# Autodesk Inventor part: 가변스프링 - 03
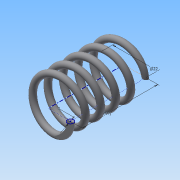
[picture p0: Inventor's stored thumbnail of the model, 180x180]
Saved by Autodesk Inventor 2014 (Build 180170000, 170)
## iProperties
Created: 2015-09
Part Number: 가변스프링 - 03
Material: 강철, 탄소
Document SubType Name: Modeling
Designer: study
Density: 7.87 g/cm^3
Appearance: 반연마
Mass: 18.806 g
Surface Area: 32.4556 cm^2
Volume: 2.38958 cm^3
Author: study
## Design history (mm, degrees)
sketch "스케치1"
  geometry: L1 (0, 0)-(11, 0); L2 (11, 0)-(11, 29.193); L3 (11, 29.193)-(0, 29.193); L4 (0, 29.193)-(0, 0); C1 r 1.5 at (11, 0)
  constraints: 8 end point, 2 parallel, 1 centre point, 1 coincident, 1 horizontal, 1 perpendicular
  dimensions: "d0" = 22 diameter of L2 L4; "d1" = 29.19259 distance of L1.end L2.end (derived); "d2" = 3 diameter of C1
feature "코일1" sketch "스케치1" pitch "d3" = 10; turns "d5" = 5; dims "d4" = 29.19259 (= d1), "d6" = 0, angle "d7" = 90 deg, angle "d8" = 90 deg, "d9" = 0, "d10" = 0
node "작업 평면1"
sketch "스케치2"
  geometry: L1 (-12.5, 0)-(-9.5, 0) reference; 1 further point
  constraints: 1 horizontal alignment
extrude "돌출1" cut sketch "스케치2" stored distance "d12" = 10; taper "d13" = 0 deg
node "작업 평면2"
sketch "스케치3"
  geometry: L1 (-9.5, 0)-(-12.5, 0) reference; 1 further point
  constraints: 1 horizontal alignment
extrude "돌출2" cut sketch "스케치3" stored distance "d15" = 10; taper "d16" = 0 deg
node "솔리드1"
node "절단 모서리 투영1"
node "절단 모서리 투영2"
other parameters: "d11" = 0, "d14" = 29.19259 (= d1)
